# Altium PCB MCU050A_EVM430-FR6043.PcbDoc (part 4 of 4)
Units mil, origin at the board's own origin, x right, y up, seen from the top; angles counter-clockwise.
Board outline 6000 x 4000 mil, 4 copper layers (Top Layer, GND, PWR, Bottom Layer), stack 61.2 mil thick; 337 components, 255 nets, 1099 pads, 437 vias.
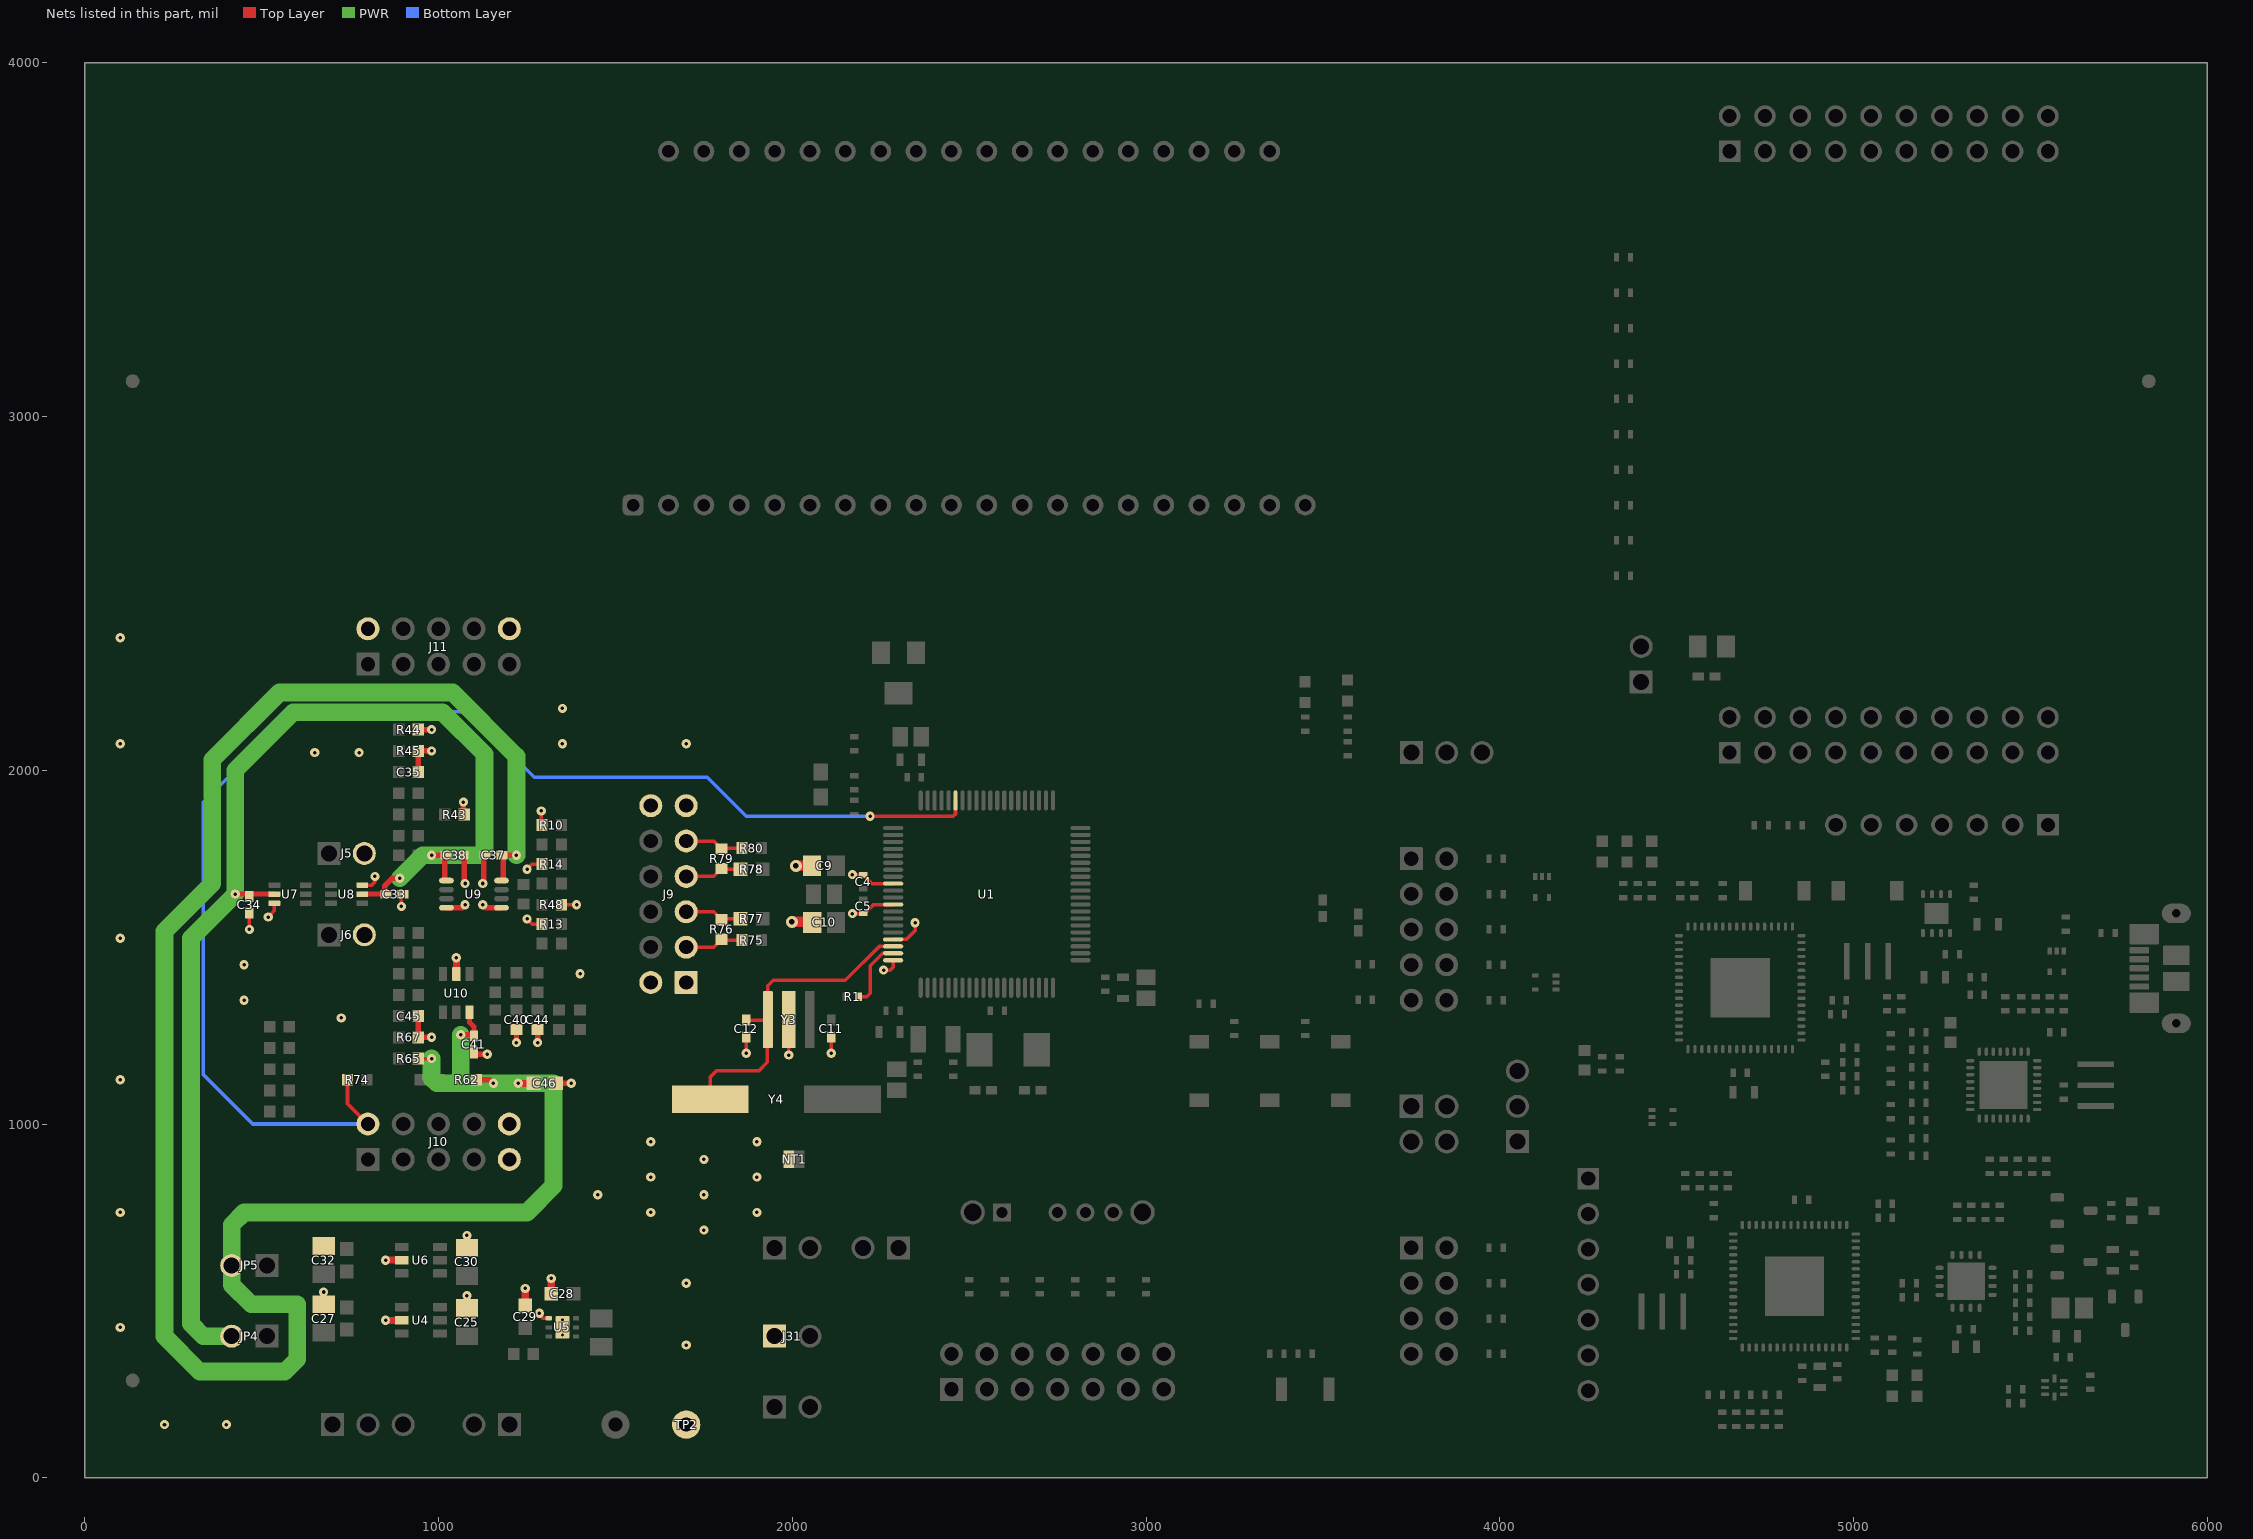
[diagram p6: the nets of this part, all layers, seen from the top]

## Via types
v1: diameter 26, hole 10, Top Layer to Bottom Layer, tented both sides, 173 vias
v2: diameter 34, hole 16, Top Layer to Bottom Layer, tented both sides, 142 vias
v3: diameter 31.5, hole 11.81, Top Layer to Bottom Layer, tented both sides, 56 vias
v4: diameter 19.68, hole 7.87, Top Layer to Bottom Layer, tented both sides, 35 vias
v5: diameter 50, hole 28, Top Layer to Bottom Layer, tented both sides, 23 vias
v6: diameter 19.68, hole 7.87, Top Layer to Bottom Layer, 7 vias
v7: diameter 34, hole 16, Top Layer to Bottom Layer, 1 vias

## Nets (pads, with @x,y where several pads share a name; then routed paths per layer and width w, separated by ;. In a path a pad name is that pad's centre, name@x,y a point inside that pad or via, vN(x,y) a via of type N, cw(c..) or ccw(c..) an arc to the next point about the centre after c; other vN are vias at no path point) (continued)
USS_GND: C4.1 C5.2 C9.1 C10.2 C11.2 C12.2 C25.2 C27.2 C28.2 C29.2 C30.2 C32.2 C33.1 C34.1 C35.1 C37.2 C38.1 C40.1 C41.1 C44.2 C45.1 C46.2 J5.2 J6.2 J9.1 J9.2 J9.11 J9.12 J10.9 J10.10 J11.2 J11.10 J31.1 NT1.1 R10.1 R13.1 R14.1 R43.2 R44.1 R45.1 R48.1 R67.1 TP2.1 U1.69 U1.72 U1.77 U1.80 U4.2 U5.1 U5.7@1350,425 U6.2 U7.3 U8.3 U9.4 U9.5 U10.2 Y3.2 | length 2145
  Top Layer w10: v1(465,1550) C34.1@465,1596.38 ; v1(518.15,1585) 535.71,1602.56 U7.3@535.71,1624.41 ; U8.3@784.29,1675.59 810.59,1675.59 820,1685 v1(820,1700) ; v1@895,1610 v1(895,1615) 895,1646.38 C33.1@898.62,1650 ; v1(1250,1580) 1265,1565 R13.1@1292.44,1565 ; v1(1250,1720) 1265,1735 R14.1@1292.44,1735 ; v1(1285,465) 1285,460 1294.41,450.59 U5.1@1311.61,450.59 ; v1(1290,1885) 1290,1847.44 R10.1@1292.44,1845 ; R48.1@1347.56,1620 v1(1390,1620) ; v1(1870,1200) C12.2@1870,1246.38 ; v1(1990,1195) Y3.2@1990,1295 ; v1(2110,1200) C11.2@2110,1246.38 ; v1(2170,1595) C5.2@2200,1595 ; v1(2170,1705) C4.1@2200,1705 2225.47,1679.53 U1.69@2285.24,1679.53 ; C5.2@2205,1595 2230.47,1620.47 U1.72@2285.24,1620.47 ; v1(2258,1435) 2276.47,1435 2285.24,1443.76 U1.80@2285.24,1462.99 ; U1.77@2285.24,1522.05 2323.05,1522.05 2347,1546 v1(2347,1569)
  Top Layer w15: C45.1@942.56,1305 R67.1@942.56,1245 v1(980,1245) ; C35.1@942.56,1995 R45.1@942.56,2055 v1(980,2055) ; R44.1@942.56,2115 v1(980,2115) ; U9.4@1022.24,1611.61 1066.61,1611.61 v1(1075,1620) ; v1(1070,1910) 1070,1877.56 R43.2@1072.56,1875 ; C38.1@1072.56,1760 1072.56,1682.44 v1(1075,1680) ; C41.1@1100,1197.44 v1(1137.44,1197.44) ; v1(1125,1620) 1133.39,1611.61 U9.5@1177.76,1611.61 ; v1(1125,1680) 1127.44,1682.44 C37.2@1127.44,1760 ; v1(1220,1230) C40.1@1220,1267.44 ; v1(1280,1230) C44.2@1280,1267.44 ; C46.2@1331.5,1115 v1(1375,1115)
  Top Layer w20: C27.2@675,481.49 v1(675,525) ; v1(850,445) U4.2@895.86,445 ; v1(850,615) U6.2@895.86,615 ; U10.2@1050,1424.13 v1(1050,1470) ; C25.2@1079.99,471.49 v1(1080,515) ; C30.2@1080,641.49 v1(1080,685) ; C29.2@1245,486.49 v1(1245,535) ; C28.2@1318.5,520 v1(1318.5,563.5)
  Top Layer w30: v2(1998.62,1571.42) C10.2@2045.12,1571.42 ; v2(2010,1730) C9.1@2060.16,1730
  other v1: 225,150 400,150 1700,375 100,425 1700,550 1750,700 100,750 1600,750 1900,750 1450,800 1750,800 1600,850 1900,850 1750,900 1600,950 1900,950 100,1125 725,1300 450,1350 1400,1425 450,1450 100,1525 650,2050 775,2050 100,2075 1350,2075 1700,2075 1350,2175 100,2375
  other v6: 1350,403.35 1350,446.65
USSXTIN: C12.1 U1.78 Y3.3 Y4.1 | length 918.7
  Top Layer w10: Y4.1@1767.99,1070 1767.99,1132.99 1785,1150 1905,1150 1929.57,1174.57 Y3.3@1929.57,1293.62 ; C12.1@1870,1293.62 Y3.3@1929.57,1293.62 ; U1.78@2285.24,1502.36 2246.36,1502.36 2150,1406 1946,1406 1930.94,1390.94 Y3.3@1930.94,1295 Y3.3@1929.57,1293.62
USSXTOUT: R1.2 U1.79 | length 191.4
  Top Layer w10: R1.2@2190,1360 2210,1360 2220,1370 2220,1447.37 2255.3,1482.68 U1.79@2285.24,1482.68
VCC-RX: C37.1 C41.2 C46.1 JP5.2 R62.1 R65.2 U9.8 U10.6 | length 6076.6
  Top Layer w10: R65.2@942.56,1185 v1(980,1185)
  Top Layer w15: v1(1062.44,1252.56) 1100,1252.56 1100,1275 1087.4,1287.6 U10.6@1087.4,1315.87 ; R62.1@1107.56,1125 1145,1125 v1(1155,1115) ; C37.1@1178.62,1760 C37.1@1182.56,1760 ; U9.8@1182.56,1693.19 C37.1@1182.56,1760 ; v1(1220,1760) C37.1@1182.56,1760
  Top Layer w20: v1(1225,1115) C46.1@1268.5,1115
  PWR w50: v1(980,1185) 980,1130 995,1115 v1(1155,1115) v1(1225,1115) 1325,1115 1325,825 1250,750 450,750 415,715 JP5.2@415,600 415,545 470,490 600,490 600,335 565,300 325,300 225,400 225,1545 360,1680 360,2030 550,2220 1040,2220 1220,2040 v1(1220,1760) ; 1062.44,1117.44 v1(1062.44,1252.56)
VCC-TX: C33.2 C34.2 C38.2 JP4.2 U7.2 U8.2 U9.1 | length 3459.8
  Top Layer w15: v1(425,1650) U7.2@535.71,1650 ; U8.2@784.29,1650 847.44,1650 847.44,1672.44 870,1695 v1(890,1695) ; v1(980,1760) C38.2@1017.44,1760 ; C38.2@1021.38,1760 C38.2@1017.44,1760 ; U9.1@1022.24,1688.39 1017.44,1693.19 C38.2@1017.44,1760
  PWR w50: JP4.2@400,400 335,400 300,435 300,1525 v1(425,1650) 425,2000 589,2164 1011,2164 1130,2045 1130,1775 1115,1760 v1(980,1760) 955,1760 v1(890,1695)
X_CH0_IN: J9.3 R75.2 R76.2 | length 164.3
  Top Layer w10: J9.3@1700,1500 1777.56,1500 R76.2@1800,1522.44 ; R76.2@1802.44,1520 R75.2@1857.44,1520
X_CH0_OUT: J9.5 R76.1 R77.2 | length 164.3
  Top Layer w10: J9.5@1700,1600 1777.56,1600 R76.1@1800,1577.56 ; R76.1@1802.44,1580 R77.2@1857.44,1580
X_CH1_IN: J9.9 R79.1 R80.2 | length 167.7
  Top Layer w10: J9.9@1700,1800 1777.56,1800 R79.1@1800,1777.56 1802.44,1780 R80.2@1857.44,1780
X_CH1_OUT: J9.7 R78.2 R79.2 | length 167.7
  Top Layer w10: J9.7@1700,1700 1777.56,1700 R79.2@1800,1722.44 1802.44,1720 R78.2@1857.44,1720
XPB0: J10.2 R74.2 U1.55 | length 3837.1
  Top Layer w10: R74.2@742.44,1125 742.44,1057.56 J10.2@800,1000 ; v1(2220,1870) 2455,1870 2461.42,1876.42 U1.55@2461.42,1914.76
  Bottom Layer w10: J10.2@800,1000 475,1000 335,1140 335,1910 590,2165 1085,2165 1270,1980 1760,1980 1870,1870 v1(2220,1870)
pads on no net: FID1.1 FID2.1 FID3.1 H1.0 H2.0 H3.0 H4.0 J7.2 J7.3 J7.6 J7.8 J7.10 J7.11 J7.12 J7.14 J7.15 J7.16 J7.18 J7.20 J8.1 J8.3 J8.4 J8.5 J8.7 J8.8 J8.9 J8.10 J8.11 J8.13 J8.15 J8.16 J8.17 J8.18 J8.19 J11.3 J11.4 J11.5 J11.6 J11.7 J11.8 J12.4 J34.6 J34.10 J34.13 LBL1.0 LCD.25 LCD.26 LCD.27 LCD.28 LCD.29 LCD.30 LCD.31 SH-J1.0 SH-J2.0 SH-J3.0 SH-J4.0 SH-J5.0 SH-J6.0 SH-J7.0 SH-J8.0 SH-J9.0 SH-J10.0 SH-J11.0 SH-J12.0 SH-J13.0 SH-J14.0 SH-J15.0 SH-J16.0 SH-J17.0 SH-J18.0 U4.3 U5.7@1350,407.28 U5.7@1350,442.72 U6.3 U100.3 U100.4 U100.10 U100.12 U100.13 U100.18 U100.19 U100.22 U100.23 U100.24 U100.25 U100.29 U100.30 U100.31 U100.32 U100.33 U100.36 U100.41 U100.42 U100.45 U100.46 U100.47 U100.48 U200.1 U200.2 U200.3 U200.4 U200.5 U200.6 U200.7 U200.8 U200.9 U200.10 U200.12 U200.13 U200.18 U200.19 U200.20 U200.21 U200.22 U200.23 U200.24 U200.28 U200.29 U200.30 U200.31 U200.33 U200.36 U200.41 U200.42 U200.43 U200.44 U200.45 U200.46 U200.47 U200.48 U400.2 U401.5 U401.9 U401.13 U401.17 U401.21 U401.32 U402.2 U402.6 U402.7

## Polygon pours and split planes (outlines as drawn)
TARGET_GND on Bottom Layer "BOTTOM_LAYER_TARGET_GND_P049" (solid, remove dead copper, pour order 49): 0,0 0,4000 6000,4000 6000,0
USS_GND on Bottom Layer "BOTTOM_LAYER_USS_GND_P048" (solid, remove dead copper, pour order 48): 1570,2500 0,2500 0,0 2000,0 2000,1000 2170,1000 2170,1319.3 2365,1477.27 2365,1705
TARGET_GND on GND "GND_TARGET_GND_P043" (solid, remove dead copper, pour order 43): 0,0 0,4000 6000,4000 6000,0
USS_GND on GND "GND_USS_GND_P042" (solid, remove dead copper, pour order 42): 1570,2500 0,2500 0,0 2000,0 2000,1000 2170,1000 2170,1319.3 2365,1477.27 2365,1705
TARGET_GND on Top Layer "TOP_LAYER_TARGET_GND_P045" (solid, remove dead copper, pour order 45): 0,0 0,4000 6000,4000 6000,0
USS_GND on Top Layer "TOP_LAYER_USS_GND_P044" (solid, remove dead copper, pour order 44): 1570,2500 0,2500 0,0 2000,0 2000,1000 2170,1000 2170,1319.3 2365,1477.27 2365,1705
TARGET_GND on PWR "PWR_TARGET_GND_P047" (solid, remove dead copper, pour order 47): 0,0 0,4000 6000,4000 6000,0
USS_GND on PWR "PWR_USS_GND_P046" (solid, remove dead copper, pour order 46): 1570,2500 0,2500 0,0 2000,0 2000,1000 2170,1000 2170,1319.3 2365,1477.27 2365,1705

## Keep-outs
Keep-Out Layer:
  the board outline again, w10
  text ".Layer_Name" at 577,-858.49 h60

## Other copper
Top Layer:
  rectangle net USS_GND: 1055,1600 1145,1700
  pour cut-out: 560.31,1900 1317.2,1900 1317.2,1450 560.31,1450
  text ".Layer_Name" at 577,-858.49 h60
GND:
  rectangle net USS_GND: 795,1672.44 847.44,1722.81
  rectangle net USS_GND: 870,1590 920,1638.19
  rectangle net USS_GND: 1037,1439 1063,1491.67
  rectangle net USS_GND: 1020,1455 1078.75,1495
  text ".Layer_Name" at 577,-858.49 h60
PWR:
  text ".Layer_Name" at 577,-858.49 h60
Bottom Layer:
  text ".Layer_Name" at 577,-858.49 h60
Multi-Layer:
  pour cut-out: 1305,1455 1063,1455 1063,1390 1015,1390 990,1365 990,1287.32 1037.76,1287.32 1037.76,1345.29 1139.33,1345.29 1139.33,1305 1180.67,1305 1180.67,1345.29 1250,1345.29 1250,1405 1305,1405
  pour cut-out: 920,1455 1037,1455 1037,1400 970,1400 970,1340 920,1340
  pour cut-out: 1040,1850 920,1850 920,1960 970,1960 970,1900 1040,1900
  pour cut-out: 910,1905 650,1905 560.31,1815.31 560.31,1489.68 655,1395 910,1395 910,1570 860,1570 860,1450 759.68,1450 759.68,1850 860,1850 860,1735 910,1735

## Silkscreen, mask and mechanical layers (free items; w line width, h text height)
Top Overlay:
  lines w8: 625,1870 680,1870 690,1860 690,1845 ; 630,1425 670,1425 690,1445 690,1450 690,1470 ; 685,1370 700,1370 760,1430 760,1470 ; 685,1930 700,1930 760,1870 760,1835 ; 4330,880 5970,880
  text "GND" at 4656.5,3921.5 h35 r90
  text "NC" at 4761.5,3921.5 h35 r90
  text "PJ.1" at 4861.5,3921.5 h35 r90
  text "NC" at 4961.5,3921.5 h35 r90
  text "NC" at 5061.5,3921.5 h35 r90
  text "PJ.2" at 5161.5,3921.5 h35 r90
  text "PJ.3" at 5261.5,3921.5 h35 r90
  text "NC" at 5361.5,3921.5 h35 r90
  text "NC" at 5461.5,3921.5 h35 r90
  text "P4.0" at 5561.5,3921.5 h35 r90
  text "NC" at 4761.5,3641.5 h35 r90
  text "NC" at 4861.5,3641.5 h35 r90
  text "NC" at 4961.5,3641.5 h35 r90
  text "NC" at 5061.5,3641.5 h35 r90
  text "NC" at 5161.5,3641.5 h35 r90
  text "NC" at 5261.5,3641.5 h35 r90
  text "NC" at 5361.5,3641.5 h35 r90
  text "NC" at 5461.5,3641.5 h35 r90
  text "NC" at 5561.5,3641.5 h35 r90
  text "NC" at 4661.5,3636.5 h35 r90
  text "'.PRJ_Number'" at 335,3475 h72.83
  text "PCB Rev '.PCB_Rev'" at 355,3180 h72.83
  text "Limited BoosterPack support." at 5045,2505 h72.83 r90
  text "GND" at 600,2380 h72.83
  text "GND" at 1265,2380 h72.83
  text "VCC_TX" at 475,2275 h72.83
  text "VCC_RX" at 1265,2275 h72.83
  text "See ti.com/tool/EVM430-FR6043 for a full list" at 5125,2265 h72.83 r90
  text "NC" at 4660,2215 h35 r90
  text "GND" at 4760,2215 h35 r90
  text "NC" at 4860,2215 h35 r90
  text "NC" at 4960,2215 h35 r90
  text "NC" at 5060,2215 h35 r90
  text "NC" at 5160,2215 h35 r90
  text "NC" at 5260,2215 h35 r90
  text "NC" at 5360,2215 h35 r90
  text "NC" at 5460,2215 h35 r90
  text "NC" at 5560,2215 h35 r90
  text "1" at 3680,2100 h50
  text "USS AFE" at 1205,2095 h72.83
  text "NC" at 4760,1925 h35 r90
  text "P1.3" at 4860,1925 h35 r90
  text "P1.2" at 4960.37,1925 h35 r90
  text "P3.1" at 5060,1925 h35 r90
  text "NC" at 5160,1925 h35 r90
  text "P7.0" at 5260,1925 h35 r90
  text "NC" at 5360,1925 h35 r90
  text "P1.7" at 5460,1925 h35 r90
  text "P1.6" at 5560,1925 h35 r90
  text "GND" at 530,1910 h72.83
  text "GND" at 1760,1905 h60
  text "GND" at 1425,1900 h60
  text "3.3V" at 4665,1895 h45 r90
  text "X1" at 535,1850 h72.83
  text "R1" at 1480,1785 h60
  text "IRQ" at 3685,1723.21 h45 r90
  text "T1" at 1480,1680 h60
  text "USB" at 5725,1635 h72.83
  text "SCL" at 3685,1623.21 h45 r90
  text "T0" at 1480,1580 h60
  text "SDA" at 3685,1523.21 h45 r90
  text "R0" at 1480,1480 h60
  text "RXD" at 3685,1423.21 h45 r90
  text "X2" at 535,1405 h72.83
  text "GND" at 530,1350 h72.83
  text "TXD" at 3685,1325 h45 r90
  text "GND" at 1615,1225 h60 r90
  text "GND" at 1720,1220 h60 r90
  text "Left" at 3100,980 h72.83
  text "Right" at 3280,980 h72.83
  text "Select" at 3470,980 h72.83
  text "GND" at 1265,975 h72.83
  text "HID-BRIDGE" at 4555,925 h72.83
  text "USB-COMM" at 5275,925 h72.83
  text "GND" at 1265,875 h72.83
  text "EXT" at 2670,860 h72.83 r90
  text "EZFET" at 2785,860 h72.83 r90
  text "JTAG" at 2895,860 h72.83 r90
  text "1" at 4000,850 h50
  text "GND" at 3645,830 h72.83
  text "GND" at 3815,830 h72.83
  text "EZFET-LITE" at 4920,810 h72.83
  text "GPIOS" at 910,780 h72.83
  text "POWER" at 3030,735 h72.83
  text "AFE_VCC" at 1815,730 h70
  text "MCU_VCC" at 2145,730 h70
  text "VCC_RX" at 340,675 h72.83
  text "SELECT" at 3030,675 h72.83
  text "RST" at 3560,625 h72.83
  text "TEST" at 3525,525 h72.83
  text "AFE" at 1900,515 h50
  text "MCU" at 2020,515 h50
  text "GND" at 1895,475 h50
  text "GND" at 2020,475 h50
  text "RXD" at 3560,425 h72.83
  text "TXD" at 3560,330 h72.83
  text "VCC_TX" at 335,285 h72.83
  text "|3.3VTX|" at 610,225 h72.83
  text "AFE3V3" at 1380,220 h72.83
  text "GND" at 1650,220 h72.83
  text "MCU_RESET" at 3280,130 h72.83
  text "EXT" at 1900,105 h50
  text "MCU" at 2030,105 h50
  text "PWR" at 1890,65 h50
  text "GND" at 2030,65 h50
  text "JTAG" at 2670,60 h72.83
  text "|5VTX|" at 750,40 h72.83
  text "5VENA" at 1045,30 h72.83
  text ".Layer_Name" at 577,-858.49 h60
Bottom Overlay:
  text ".Layer_Name" at 577,-858.49 h60
Top Paste:
  text ".Layer_Name" at 577,-858.49 h60
Bottom Paste:
  text ".Layer_Name" at 577,-858.49 h60
Top Solder:
  text ".Layer_Name" at 577,-858.49 h60
  text ".Layer_Name" at 577,-858.49 h60
Bottom Solder:
  text ".Layer_Name" at 577,-858.49 h60
Drill Guide:
  text ".Layer_Name" at 577,-858.49 h60
M1 Board Outline:
  the board outline again, w10
  text ".Layer_Name" at 577,-858.49 h60
M2 Board Dimensions:
  rectangle: 0,-275 125,-150
  rectangle: 125,-400 500,-275
  lines w7: 0,-275 1000,-275 ; 125,-400 125,-150 ; 250,-400 250,-150 ; 500,-400 500,-150 ; 750,-400 750,-150 ; 0,-400 1000,-400 1000,-150 0,-150 0,-400
  text ".Layer_Name" at 577,-858.49 h60
M3 3D STEP Top:
  text ".Layer_Name" at 577,-858.49 h60
M4 3D STEP Bottom:
  text ".Layer_Name" at 577,-858.49 h60
M5 Assembly Top:
  lines w10: -292,-930.17 6308,-930.17 ; -292,-726.83 6310,-726.83 ; -292,-523.5 -292,-1133.5 3713,-1133.5 6310,-1133.5 6310,-523.5 -291.5,-523.5 -291.5,-1133.5 1284,-1133.5 ; 2173,-1133.5 2173,-523.5 ; 3440,-726.83 3440,-523.5 ; 4280,-726.83 4280,-523.5 ; 4902,-1140 4902,-937.17
  text "COMPONENTS MARKED 'DNP' SHOULD NOT BE POPULATED." at 1153.5,-318.5 h60
  text "ASSEMBLY VARIANT:" at 1153,-434 h60
  text ".VariantName" at 2189,-434 h60
  text "PCB VIEWED FROM TOP SIDE" at -228.5,-655.67 h60
  text "BOARD #:" at 2248,-655.67 h60
  text ".PRJ_Number" at 2793.5,-655.67 h60
  text "REV:" at 3638,-655.67 h60
  text ".PCB_Rev" at 3929.5,-655.67 h60
  text "SVN REV:" at 4476,-655.67 h60
  text ".VersionControl_RevNumber" at 4982,-655.67 h60
  text "TID #:" at 2248,-859 h60
  text ".TID" at 2793.5,-859 h60
  text "PLOT NAME =" at -228.5,-1064.34 h60
  text ".plot_File_Name" at 577,-1064.34 h60
  text "GENERATED    :" at 2250,-1064.34 h60
  text ".Print_Date" at 3119.5,-1064.34 h60
  text ".Print_Time" at 3848.5,-1064.34 h60
  text "TEXAS INSTRUMENTS" at 5113,-1064.34 h60
M6 Assembly Bottom:
  lines w10: -292.5,-727.33 6309.5,-727.33 ; -290.5,-930.67 6309.5,-930.67 ; 1115.5,-1140.5 1115.5,-937.67 ; 1737.5,-727.33 1737.5,-524 ; 2577.5,-727.33 2577.5,-524 ; 3844.5,-1134 3844.5,-524 ; 4733.5,-1134 6309,-1134 6309,-524 -292.5,-524 -292.5,-1134 2304.5,-1134 6309.5,-1134 6309.5,-524
  text "COMPONENTS MARKED 'DNP' SHOULD NOT BE POPULATED." at 6102,-318 h60
  text ".VariantName" at 5058,-434 h60
  text "ASSEMBLY VARIANT:" at 6097,-434 h60
  text ".VersionControl_RevNumber" at 1035.5,-656.17 h60
  text "SVN REV:" at 1541.5,-656.17 h60
  text ".PCB_Rev" at 2088,-656.17 h60
  text "REV:" at 2379.5,-656.17 h60
  text ".PRJ_Number" at 3224,-656.17 h60
  text "BOARD #:" at 3769.5,-656.17 h60
  text "PCB VIEWED FROM BOTTOM SIDE" at 6246,-656.17 h60
  text ".TID" at 3224,-859.5 h60
  text "TID #:" at 3769.5,-859.5 h60
  text "TEXAS INSTRUMENTS" at 904.5,-1064.84 h60
  text ".Print_Time" at 2169,-1064.84 h60
  text ".Print_Date" at 2898,-1064.84 h60
  text "GENERATED    :" at 3767.5,-1064.84 h60
  text ".plot_File_Name" at 5440.5,-1064.84 h60
  text "PLOT NAME =" at 6246,-1064.84 h60
M9 Title Sheet:
  drawing of 57 lines, arcs and shapes, not listed
  text "1" at 739.84,8036.5 h70
  text "2" at 3235.5,8036.5 h70
  text "3" at 5724.84,8036.5 h70
  text "4" at 8231.51,8036.5 h70
  text "5" at 10730.5,8036.5 h70
  text "6" at 13235.5,8036.5 h70
  text "A" at -416.5,6893.5 h70
  text "A" at 14383.5,6893.5 h70
  text "B" at -416.5,4513.5 h70
  text "B" at 14383.5,4513.5 h70
  text "C" at -416.5,2138.5 h70
  text "C" at 14383.5,2138.5 h70
  text "PROJECT TITLE:" at 11343.5,277.5 h45
  text ".PRJ_Title" at 11393.5,144.17 h70
  text "DESIGNED FOR:" at 11343.5,-23.5 h45
  text ".PRJ_Customer" at 11393.5,-163.5 h70
  text "D" at -416.5,-231.5 h70
  text "D" at 14383.5,-231.5 h70
  text "FILE NAME:" at 11343.5,-323.5 h45
  text ".PCB_File_Name_No_Path" at 11393.5,-443.5 h70
  text "Texas Instruments (TI) and/or its licensors do not warrant the accuracy or completeness of this specification" at 6374,-605.34 h45
  text "ENGINEER:" at 11343.5,-613.5 h45
  text "LAYOUT BY:" at 12848.5,-613.5 h45
  text "or any information contained therein. TI and/or its licensors do not warrant that this design will meet" at 6329.01,-718 h45
  text ".PRJ_Engineer" at 11393.5,-768.49 h70
  text ".PCB_Layout" at 12899,-768.49 h70
  text "the specifications, will be suitable for your application or fit for any particular purpose, or will operate in" at 6329.01,-830.67 h45
  text ".Layer_Name" at 577,-858.49 h60
  text "ALTIUM DESIGNER VERSION:" at 12848.5,-923.5 h45
  text "an implementation. TI and/or its licensors do not warrant that the design is production worthy. You should" at 6329.01,-943.33 h45
  text "completely validate and test your design implementation to confirm the system functionality for your application." at 6374,-1056 h45
  text ".print_Scale" at 11393.5,-1056.83 h70
  text ".Application_BuildNumber" at 12899,-1056.83 h70
  text "1" at 739.84,-1263.5 h70
  text "2" at 3235.5,-1263.5 h70
  text "3" at 5724.84,-1263.5 h70
  text "4" at 8231.51,-1263.5 h70
  text "5" at 10730.5,-1263.5 h70
  text "6" at 13235.5,-1263.5 h70
M10 Fab Notes:
  drawing of 173 lines, arcs and shapes, not listed
  text "DESIGN INFORMATION" at 12378.02,6201 h60
  text "MIN. TRACK WIDTH:" at 11733.46,6021 h60
  text "6" at 12829.7,6021 h60
  text "MIL" at 12984.46,6021 h60
  text "MIN. CLEARANCE:" at 11733.46,5889 h60
  text "6" at 12824.7,5889 h60
  text "MIL" at 12984.46,5889 h60
  text "MIN. VIA PAD SIZE:" at 11733.46,5757 h60
  text "19.685" at 12634.71,5757 h60
  text "MIL" at 12984.46,5757 h60
  text "0.05mm (2MIL)" at 12428.46,5615.29 h60
  text "MINIMUM ANNULAR RING" at 11404.23,5611 h60
  text "EXTERNAL" at 13136.46,5611 h60
  text "PER" at 11604.23,5493 h60
  text "IPC-D-275 CLASS 2 LEVEL C" at 11824.23,5493 h60
  text "MIL, HOLES" at 13312.46,5380.71 h60
  text "+/-" at 12920,5380 h60
  text "+/-" at 13774,5380 h60
  text "REGISTRATION TOLERANCES:" at 11404.23,5375 h60
  text "METAL" at 12604,5375 h60
  text "5" at 13180.2,5375 h60
  text "3" at 14013.2,5375 h60
  text "MIL" at 14129.46,5375 h60
  text "+/-" at 13774,5262 h60
  text "HOLE SIZE TOLERANCE (UNLESS OTHERWISE SPECIFIED):" at 11404.23,5257 h60
  text "3" at 14013.2,5257 h60
  text "MIL" at 14129.46,5257 h60
  text "MATERIAL:" at 11329.46,5047.54 h60
  text "FR-4 High Tg" at 12315.9,4907.21 h60
  text "FR-408" at 11750.46,4898.64 h60
  text "OTHER" at 13238.46,4898.64 h60
  text "X" at 12161,4895 h60
  text "62 MIL (1.6mm) +/-10%" at 12070.56,4735.92 h60
  text "THICKNESS:" at 11404.23,4731.64 h60
  text "X" at 11942.4,4731.64 h60
  text "OTHER" at 13355.46,4731.64 h60
  text "TOLERANCE:" at 11404.23,4573.64 h60
  text "X" at 12243.53,4573.64 h60
  text "ANSI IPC-6012 TYPE 3 CLASS 2" at 12430.48,4573.64 h60
  text "OTHER +/-" at 12430.46,4417.64 h60
  text "BOW & TWIST:" at 11404.23,4260.64 h60
  text "X" at 12243.53,4260.64 h60
  text "ANSI IPC-6012 TYPE 3 CLASS 2" at 12430.48,4260.64 h60
  text "OTHER +/-" at 12430.46,4102.13 h60
  text "DRILLING:" at 11329.46,3963.64 h60
  text "REFERENCE:" at 11404.23,3846.64 h60
  text "X" at 12052.46,3846.64 h60
  text "AS SHOWN" at 12239.46,3846.64 h60
  text "X" at 12953.46,3846.64 h60
  text "NC_DRILL FILES" at 13090.46,3846.64 h60
  text "PTH COPPER THICKNESS:" at 11404.23,3688.64 h60
  text "X" at 12534.46,3688.64 h60
  text "20-30 um" at 12671.46,3688.64 h60
  text "OTHER" at 13388.46,3688.64 h60
  text "BOARD FINISH:" at 11329.46,3529.64 h60
  text "SILKSCREEN:" at 11484.68,3411.64 h60
  text "X" at 12433.46,3411.64 h60
  text "TOP" at 12559.46,3411.64 h60
  text "BOTTOM" at 13070.46,3411.64 h60
  text "SILKSCREEN COLOR:" at 11484.68,3244.64 h60
  text "X" at 12432.42,3244.64 h60
  text "WHITE" at 12559.46,3244.64 h60
  text "OTHER" at 13070.46,3244.64 h60
  text "X" at 13160,3095 h60
  text "GREEN" at 12690.46,3085.44 h60
  text "OTHER" at 13308.46,3085.44 h60
  text "SOLDER RESIST COLOR:" at 11484.68,3074.64 h60
  text "RED" at 13785,3070 h60
  text "X" at 12563.42,2915.44 h60
  text "MATTE" at 12690.46,2915.44 h60
  text "SEMI-GLOSS" at 13308,2914.8 h60
  text "IMMERSION GOLD (ENIG)" at 12390.46,2726.92 h60
  text "ENEPIG" at 13728,2723.64 h60
  text "SURFACE FINISH:" at 11329.46,2722.64 h60
  text "X" at 12203.51,2722.64 h60
  text "IMM. TIN/SILVER OR EQUIV" at 11659,2565.64 h60
  text "OTHER" at 13090.46,2565.64 h60
  text "ARRAY/PANEL:" at 11329.46,2386.64 h60
  text "CUT AND TRIM PER M1 BOARD OUTLINE" at 12390.46,2382.35 h60
  text "N.C. ROUTE" at 12390.46,2230.64 h60
  text "X" at 13069.46,2230.64 h60
  text "V. SCORE" at 13256.46,2230.64 h60
  text "CERTIFICATION:" at 11329.46,2093.64 h60
  text "MATERIALS AND WORKMANSHIP FOR ALL PCBS" at 12054.46,2093.64 h60
  text "TO MEET OR EXCEED THE REQUIREMENTS OF:" at 12054.46,1995.64 h60
  text "ANSI IPC-A-600F CLASS ->" at 11819.96,1859.13 h60
  text "X" at 13459.02,1859.13 h60
  text "2" at 13577.96,1859.14 h60
  text "1" at 13262.96,1857.64 h60
  text "3" at 13931.96,1857.64 h60
  text "X" at 12495.02,1699.64 h60
  text "RoHS" at 12631.96,1699.64 h60
  text "OTHER" at 13276.36,1699.64 h60
  text "PER ORDER" at 13673.42,1699.64 h60
  text "ALL BOARDS MUST MEET OR EXCEED UL94-V0 REQUIREMENTS." at 11357,1534 h60
  text "PCB MUST BEAR THE UL94V-0 UL REGISTERED MATERIAL ID NUMBER" at 11357,1414 h60
  text "ADDITIONAL REQUIREMENTS:" at 11329.46,1240.64 h60
  text "MICROSECTION:" at 11404.23,1125.64 h60
  text "YES" at 12309.96,1125.64 h60
  text "REQUIRED" at 13171.46,969.49 h60
  text "BARE BOARD ELEC. TEST:" at 11404.23,966.64 h60
  text "NONE" at 12709.96,966.64 h60
  text "X" at 13044.46,966.64 h60
  text "PER ORDER" at 13763.46,966.64 h60
  text ".Layer_Name" at 577,-858.49 h60
M11 Gerber Information:
  lines w10: -292,-930.17 6308,-930.17 ; -292,-726.83 6310,-726.83 ; -292,-523.5 -292,-1133.5 3713,-1133.5 6310,-1133.5 6310,-523.5 -291.5,-523.5 -291.5,-1133.5 1284,-1133.5 ; 2173,-1133.5 2173,-523.5 ; 3440,-726.83 3440,-523.5 ; 4280,-726.83 4280,-523.5 ; 4902,-1140 4902,-937.17
  text "ALL ARTWORK VIEWED FROM TOP SIDE" at -228.5,-655.67 h60
  text "BOARD #:" at 2248,-655.67 h60
  text ".PRJ_Number" at 2793.5,-655.67 h60
  text "REV:" at 3638,-655.67 h60
  text ".PCB_Rev" at 3929.5,-655.67 h60
  text "SVN REV:" at 4476,-655.67 h60
  text ".VersionControl_RevNumber" at 4982,-655.67 h60
  text "LAYER NAME =" at -228.5,-858.49 h60
  text "TID #:" at 2248,-859 h60
  text ".TID" at 2793.5,-859 h60
  text "PLOT NAME =" at -228.5,-1064.34 h60
  text ".plot_File_Name" at 577,-1064.34 h60
  text "GENERATED    :" at 2250,-1064.34 h60
  text ".Print_Date" at 3119.5,-1064.34 h60
  text ".Print_Time" at 3848.5,-1064.34 h60
  text "TEXAS INSTRUMENTS" at 5113,-1064.34 h60
M12 Stackup:
  drawing of 295 lines, arcs and shapes, not listed
  text "Layer" at 9660.34,7800 h60
  text "Name" at 10070.26,7800 h60
  text "Material" at 11000,7800 h60
  text "Thickness" at 11859.77,7800 h60
  text "Constant" at 12509.6,7800 h60
  text "Board Layer Stack" at 13079.46,7800 h60
  text "1" at 9660.34,7680 h60
  text "Top Overlay" at 10070.26,7680 h60
  text "2" at 9660.34,7560 h60
  text "Top Solder" at 10070.26,7560 h60
  text "Solder Resist" at 11000,7560 h60
  text "0.40mil" at 11859.77,7560 h60
  text "3.5" at 12509.6,7560 h60
  text "3" at 9660.34,7440 h60
  text "Top Layer" at 10070.26,7440 h60
  text "Copper" at 11000,7440 h60
  text "1.40mil" at 11859.77,7440 h60
  text "4" at 9660.34,7320 h60
  text "Dielectric1" at 10070.26,7320 h60
  text "FR-4" at 11000,7320 h60
  text "4.40mil" at 11859.77,7320 h60
  text "4.2" at 12509.6,7320 h60
  text "5" at 9660.34,7200 h60
  text "GND" at 10070.26,7200 h60
  text "Copper" at 11000,7200 h60
  text "0.70mil" at 11859.77,7200 h60
  text "6" at 9660.34,7080 h60
  text "Dielectric 2" at 10070.26,7080 h60
  text "FR-4" at 11000,7080 h60
  text "48.20mil" at 11859.77,7080 h60
  text "4.2" at 12509.6,7080 h60
  text "7" at 9660.34,6960 h60
  text "PWR" at 10070.26,6960 h60
  text "Copper" at 11000,6960 h60
  text "0.70mil" at 11859.77,6960 h60
  text "8" at 9660.34,6840 h60
  text "Dielectric 3" at 10070.26,6840 h60
  text "FR-4" at 11000,6840 h60
  text "4.40mil" at 11859.77,6840 h60
  text "4.2" at 12509.6,6840 h60
  text "9" at 9660.34,6720 h60
  text "Bottom Layer" at 10070.26,6720 h60
  text "Copper" at 11000,6720 h60
  text "1.40mil" at 11859.77,6720 h60
  text "10" at 9660.34,6600 h60
  text "Bottom Solder" at 10070.26,6600 h60
  text "Solder Resist" at 11000,6600 h60
  text "0.40mil" at 11859.77,6600 h60
  text "3.5" at 12509.6,6600 h60
  text "11" at 9660.34,6480 h60
  text "Bottom Overlay" at 10070.26,6480 h60
  text ".Layer_Name" at 577,-858.49 h60
M13 Component Bodies Top:
  text ".Layer_Name" at 577,-858.49 h60
M14 Component Bodies Bottom:
  text ".Layer_Name" at 577,-858.49 h60
M15 Courtyards Top:
  text ".Layer_Name" at 577,-858.49 h60
M16 Courtyards Bottom:
  text ".Layer_Name" at 577,-858.49 h60
Drill Drawing:
  circle w10: c6618.73,3607.23 r27.63
  circle w10: c6618.73,3482.9 r16.58
  circle w10: c6618.73,3482.9 r27.63
  lines w10: 6591.1,2225.73 6604.91,2225.73 6604.91,2211.91 6632.54,2211.91 6632.54,2225.73 6646.36,2225.73 6646.36,2253.36 6632.54,2253.36 6632.54,2267.18 6604.91,2267.18 6604.91,2253.36 6591.1,2253.36 6591.1,2225.73 ; 6591.1,2350.07 6604.91,2350.07 6618.73,2336.25 6632.54,2350.07 6646.36,2350.07 6632.54,2363.88 6646.36,2377.7 6632.54,2377.7 6618.73,2391.51 6604.91,2377.7 6591.1,2377.7 6604.91,2363.88 6591.1,2350.07 ; 6591.1,2612.55 6618.73,2584.92 6646.36,2612.55 6618.73,2640.18 6591.1,2612.55 ; 6591.1,2709.26 6646.36,2709.26 6646.36,2764.52 6591.1,2764.52 6591.1,2709.26 ; 6591.1,2833.59 6646.36,2833.59 6646.36,2888.85 6591.1,2888.85 6591.1,2833.59 ; 6591.1,3013.19 6646.36,3013.19 6618.73,2957.93 6591.1,3013.19 ; 6591.1,3137.52 6646.36,3137.52 6618.73,3082.26 6591.1,3137.52 ; 6591.1,3206.6 6618.73,3220.41 6646.36,3206.6 6632.54,3234.23 6646.36,3261.86 6618.73,3248.04 6591.1,3261.86 6604.91,3234.23 6591.1,3206.6 ; 6591.1,3344.75 6604.91,3344.75 6604.91,3330.93 6632.54,3330.93 6632.54,3344.75 6646.36,3344.75 6646.36,3372.38 6632.54,3372.38 6632.54,3386.19 6604.91,3386.19 6604.91,3372.38 6591.1,3372.38 6591.1,3344.75 ; 6591.1,3703.94 6591.1,3717.75 6604.91,3731.57 6591.1,3745.38 6591.1,3759.2 6604.91,3759.2 6618.73,3745.38 6632.54,3759.2 6646.36,3759.2 6646.36,3745.38 6632.54,3731.57 6646.36,3717.75 6646.36,3703.94 6632.54,3703.94 6618.73,3717.75 6604.91,3703.94 6591.1,3703.94 ; 6602.15,2231.26 6610.44,2231.26 6610.44,2222.97 6627.02,2222.97 6627.02,2231.26 6635.3,2231.26 6635.3,2247.83 6627.02,2247.83 6627.02,2256.12 6610.44,2256.12 6610.44,2247.83 6602.15,2247.83 6602.15,2231.26 ; 6602.15,2720.31 6635.3,2720.31 6635.3,2753.46 6602.15,2753.46 6602.15,2720.31 ; 6602.15,3002.13 6635.3,3002.13 6618.73,2968.98 6602.15,3002.13
  lines w12: 6541,2174.61 9771.06,2174.61 ; 6541,3790.97 9771.06,3790.97 ; 6878.75,2050.28 6878.75,3915.31 ; 7210.56,2050.28 7210.56,3915.31 ; 7846.66,2050.28 7846.66,3915.31 ; 8105.66,2050.28 8105.66,3915.31 ; 8480.64,2050.28 8480.64,3915.31 ; 9204.86,2050.28 9204.86,3915.31 ; 6541,2050.28 9771.06,2050.28 9771.06,3915.31 6541,3915.31 6541,2050.28
  text "Symbol" at 6615.6,3828.27 h72
  text "Quantity" at 6916.05,3828.27 h72
  text "Finished Hole Size" at 7247.86,3828.27 h72
  text "Plated" at 7883.96,3828.27 h72
  text "Hole Type" at 8142.96,3828.27 h72
  text "Drill Layer Pair" at 8517.94,3828.27 h72
  text "Hole Tolerance" at 9242.16,3828.27 h72
  text "42" at 6916.05,3703.94 h60
  text "7.87mil (0.200mm)" at 7247.86,3703.94 h60
  text "PTH" at 7883.96,3703.94 h60
  text "Round" at 8142.96,3703.94 h60
  text "Top Layer - Bottom Layer" at 8517.94,3703.94 h60
  text "173" at 6916.05,3579.6 h60
  text "10.00mil (0.254mm)" at 7247.86,3579.6 h60
  text "PTH" at 7883.96,3579.6 h60
  text "Round" at 8142.96,3579.6 h60
  text "Top Layer - Bottom Layer" at 8517.94,3579.6 h60
  text "56" at 6916.05,3455.27 h60
  text "11.81mil (0.300mm)" at 7247.86,3455.27 h60
  text "PTH" at 7883.96,3455.27 h60
  text "Round" at 8142.96,3455.27 h60
  text "Top Layer - Bottom Layer" at 8517.94,3455.27 h60
  text "143" at 6916.05,3330.93 h60
  text "16.00mil (0.406mm)" at 7247.86,3330.93 h60
  text "PTH" at 7883.96,3330.93 h60
  text "Round" at 8142.96,3330.93 h60
  text "Top Layer - Bottom Layer" at 8517.94,3330.93 h60
  text "23" at 6916.05,3206.6 h60
  text "28.00mil (0.711mm)" at 7247.86,3206.6 h60
  text "PTH" at 7883.96,3206.6 h60
  text "Round" at 8142.96,3206.6 h60
  text "Top Layer - Bottom Layer" at 8517.94,3206.6 h60
  text "4" at 6916.05,3082.26 h60
  text "31.50mil (0.800mm)" at 7247.86,3082.26 h60
  text "PTH" at 7883.96,3082.26 h60
  text "Round" at 8142.96,3082.26 h60
  text "Top Layer - Bottom Layer" at 8517.94,3082.26 h60
  text "38" at 6916.05,2957.93 h60
  text "35.43mil (0.900mm)" at 7247.86,2957.93 h60
  text "PTH" at 7883.96,2957.93 h60
  text "Round" at 8142.96,2957.93 h60
  text "Top Layer - Bottom Layer" at 8517.94,2957.93 h60
  text "80" at 6916.05,2833.59 h60
  text "40.00mil (1.016mm)" at 7247.86,2833.59 h60
  text "PTH" at 7883.96,2833.59 h60
  text "Round" at 8142.96,2833.59 h60
  text "Top Layer - Bottom Layer" at 8517.94,2833.59 h60
  text "40" at 6916.05,2709.26 h60
  text "40.16mil (1.020mm)" at 7247.86,2709.26 h60
  text "PTH" at 7883.96,2709.26 h60
  text "Round" at 8142.96,2709.26 h60
  text "Top Layer - Bottom Layer" at 8517.94,2709.26 h60
  text "29" at 6916.05,2584.92 h60
  text "45.28mil (1.150mm)" at 7247.86,2584.92 h60
  text "PTH" at 7883.96,2584.92 h60
  text "Round" at 8142.96,2584.92 h60
  text "Top Layer - Bottom Layer" at 8517.94,2584.92 h60
  text "4" at 6916.05,2460.59 h60
  text "47.24mil (1.200mm)" at 7247.86,2460.59 h60
  text "PTH" at 7883.96,2460.59 h60
  text "Round" at 8142.96,2460.59 h60
  text "Top Layer - Bottom Layer" at 8517.94,2460.59 h60
  text "A" at 6590.31,2450.59 h55.26
  text "2" at 6916.05,2336.25 h60
  text "49.21mil (1.250mm)" at 7247.86,2336.25 h60
  text "PTH" at 7883.96,2336.25 h60
  text "Round" at 8142.96,2336.25 h60
  text "Top Layer - Bottom Layer" at 8517.94,2336.25 h60
  text "2" at 6916.05,2211.91 h60
  text "23.62mil (0.600mm)" at 7247.86,2211.91 h60
  text "PTH" at 7883.96,2211.91 h60
  text "Slot" at 8142.96,2211.91 h60
  text "Top Layer - Bottom Layer" at 8517.94,2211.91 h60
  text "636 Total" at 6916.05,2087.58 h60
  text "Slot definitions :" at 6615.6,2000.55 h60
  text "Routed Path Length" at 7066.08,2000.55 h60
  text "= Calculated from tool start centre position to tool end centre position." at 7605.63,2000.55 h60
  text "Hole Length" at 7066.08,1950.81 h60
  text "= Routed Path Length + Tool Size = Slot length as defined in the PCB layout" at 7405.89,1950.81 h60
  text ".Layer_Name" at 577,-858.49 h60
M17 Embedded Cavity:
  text ".Layer_Name" at 577,-858.49 h60
M18 Embedded Assembly:
  text ".Layer_Name" at 577,-858.49 h60
M19 Embedded Keepout:
  text ".Layer_Name" at 577,-858.49 h60

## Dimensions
0,0 to 0,4000 on M2 Board Dimensions
0,0 to 6000,-25 on M2 Board Dimensions
0,-400 to 1000,-400 on M2 Board Dimensions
